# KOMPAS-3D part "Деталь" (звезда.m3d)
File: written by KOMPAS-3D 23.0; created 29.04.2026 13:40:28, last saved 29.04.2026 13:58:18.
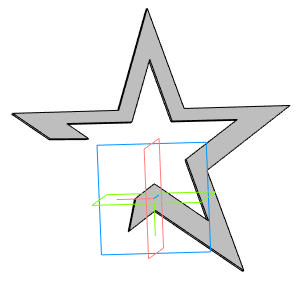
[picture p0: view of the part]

Document properties: Автор: USER; Полное имя файла: C:\Users\USER\Desktop\звезда.m3d

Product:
- Part/product: Деталь
    Масса: 0.073523

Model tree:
1. Эскиз:1
2. Элемент выдавливания:2
     Расстояние 1 = 4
